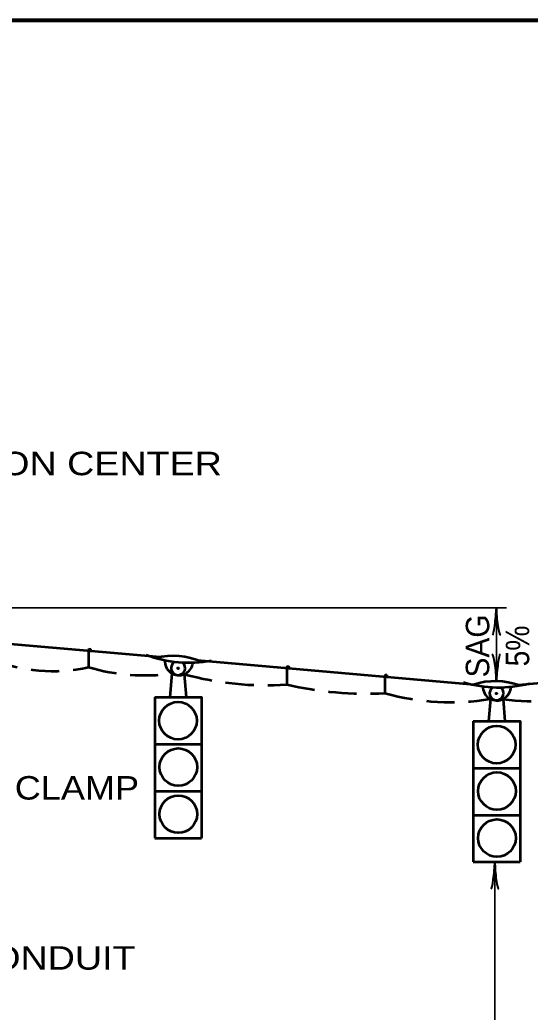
# Model space of a CAD drawing. Extents: x 14808 to 15663, y 10944 to 11488.
# Drawn here: x 15010.4 to 15075.7, y 11354.9 to 11481.7 of the extents above; entities that cross this region are included whole.
import ezdxf
from ezdxf.enums import TextEntityAlignment as Align

# ---------------------------------------------------------------- set-up
doc = ezdxf.new("R2010")
doc.units = 0
doc.header["$LTSCALE"] = 1.2
doc.linetypes.add('MEDIUM_DASHED', pattern=[4.5, 3, -1.5])
doc.layers.add('1', color=7, linetype='Continuous', lineweight=53)

msp = doc.modelspace()

# ---------------------------------------------------------------- linework, layer by layer
at = {"layer": '1', "lineweight": 35}
for p, q in [((14971.841, 11406.572), (15072.654, 11406.572)), ((15071.359, 11406.554), (15071.359, 11397.19)), ((15071.168, 11374.088), (15071.168, 11273.024))]:
    msp.add_line(p, q, dxfattribs=at)
at = {"layer": '1'}
for p, q in [((14985.033, 11404.084), (15028.363, 11400.293)), ((15158.822, 11404.102), (15074.187, 11396.698)), ((15019.242, 11401.332), (15019.221, 11401.093)), ((15019.237, 11401.272), (15019.221, 11401.093)), ((15019.237, 11401.272), (15019.416, 11401.257)), ((15019.259, 11401.331), (15019.238, 11401.092)), ((15019.253, 11401.271), (15019.238, 11401.092)), ((15019.242, 11401.332), (15019.481, 11401.311)), ((15019.277, 11401.329), (15019.256, 11401.09)), ((15019.272, 11401.269), (15019.256, 11401.09)), ((15019.295, 11401.328), (15019.274, 11401.088)), ((15019.29, 11401.268), (15019.274, 11401.088)), ((15019.313, 11401.326), (15019.292, 11401.087)), ((15019.308, 11401.266), (15019.292, 11401.087)), ((15019.322, 11401.325), (15019.301, 11401.086)), ((15019.335, 11401.324), (15019.314, 11401.085)), ((15019.33, 11401.264), (15019.314, 11401.085)), ((15019.349, 11401.323), (15019.328, 11401.084)), ((15019.344, 11401.263), (15019.328, 11401.084)), ((15019.362, 11401.322), (15019.341, 11401.083)), ((15019.372, 11401.321), (15019.351, 11401.082)), ((15019.366, 11401.261), (15019.351, 11401.082)), ((15019.39, 11401.319), (15019.369, 11401.08)), ((15019.385, 11401.259), (15019.369, 11401.08)), ((15019.408, 11401.318), (15019.387, 11401.079)), ((15019.402, 11401.258), (15019.387, 11401.078)), ((15019.422, 11401.316), (15019.401, 11401.077)), ((15019.416, 11401.257), (15019.401, 11401.077)), ((15019.435, 11401.315), (15019.414, 11401.076)), ((15019.446, 11401.314), (15019.425, 11401.075)), ((15019.458, 11401.313), (15019.437, 11401.074)), ((15019.47, 11401.312), (15019.449, 11401.073)), ((15019.481, 11401.311), (15019.461, 11401.072)), ((15019.221, 11401.093), (15019.401, 11401.077)), ((15019.221, 11401.093), (15019.221, 11398.993)), ((15019.221, 11401.093), (15019.461, 11401.072)), ((15033.144, 11399.874), (15068.526, 11396.779)), ((15044.577, 11399.117), (15044.556, 11398.877)), ((15044.572, 11399.057), (15044.556, 11398.877)), ((15044.556, 11398.877), (15044.735, 11398.862)), ((15044.556, 11398.877), (15044.556, 11396.777)), ((15044.556, 11398.877), (15044.795, 11398.856)), ((15044.593, 11399.115), (15044.572, 11398.876)), ((15044.572, 11399.057), (15044.751, 11399.041)), ((15044.588, 11399.055), (15044.572, 11398.876)), ((15044.577, 11399.117), (15044.816, 11399.096)), ((15044.611, 11399.114), (15044.59, 11398.874)), ((15044.606, 11399.054), (15044.59, 11398.874)), ((15044.629, 11399.112), (15044.608, 11398.873)), ((15044.624, 11399.052), (15044.608, 11398.873)), ((15044.647, 11399.11), (15044.626, 11398.871)), ((15044.642, 11399.051), (15044.626, 11398.871)), ((15044.657, 11399.11), (15044.636, 11398.871)), ((15044.669, 11399.109), (15044.649, 11398.869)), ((15044.664, 11399.049), (15044.649, 11398.869)), ((15044.683, 11399.107), (15044.662, 11398.868)), ((15044.678, 11399.047), (15044.662, 11398.868)), ((15044.696, 11399.106), (15044.675, 11398.867)), ((15044.706, 11399.105), (15044.685, 11398.866)), ((15044.701, 11399.045), (15044.685, 11398.866)), ((15044.724, 11399.104), (15044.703, 11398.865)), ((15044.719, 11399.044), (15044.703, 11398.864)), ((15044.742, 11399.102), (15044.721, 11398.863)), ((15044.737, 11399.042), (15044.721, 11398.863)), ((15044.756, 11399.101), (15044.735, 11398.862)), ((15044.751, 11399.041), (15044.735, 11398.862)), ((15044.769, 11399.1), (15044.748, 11398.861)), ((15044.781, 11399.099), (15044.76, 11398.86)), ((15044.793, 11399.098), (15044.772, 11398.859)), ((15044.805, 11399.096), (15044.784, 11398.857)), ((15044.816, 11399.096), (15044.795, 11398.856)), ((15029.878, 11398.178), (15029.613, 11395.151)), ((15031.457, 11398.102), (15031.715, 11395.151)), ((15057.129, 11398.018), (15057.108, 11397.779)), ((15057.124, 11397.959), (15057.108, 11397.779)), ((15057.108, 11397.779), (15057.287, 11397.764)), ((15057.108, 11397.779), (15057.108, 11395.679)), ((15057.108, 11397.779), (15057.347, 11397.758)), ((15057.145, 11398.017), (15057.124, 11397.778)), ((15057.124, 11397.959), (15057.303, 11397.943)), ((15057.14, 11397.957), (15057.124, 11397.778)), ((15057.129, 11398.018), (15057.368, 11397.997)), ((15057.163, 11398.015), (15057.142, 11397.776)), ((15057.158, 11397.956), (15057.142, 11397.776)), ((15057.181, 11398.014), (15057.16, 11397.775)), ((15057.176, 11397.954), (15057.16, 11397.775)), ((15057.2, 11398.012), (15057.178, 11397.773)), ((15057.194, 11397.952), (15057.178, 11397.773)), ((15057.209, 11398.011), (15057.188, 11397.772)), ((15057.222, 11398.01), (15057.201, 11397.771)), ((15057.216, 11397.95), (15057.201, 11397.771)), ((15057.235, 11398.009), (15057.214, 11397.77)), ((15057.23, 11397.949), (15057.214, 11397.77)), ((15057.248, 11398.008), (15057.227, 11397.769)), ((15057.258, 11398.007), (15057.237, 11397.768)), ((15057.253, 11397.947), (15057.237, 11397.768)), ((15057.276, 11398.005), (15057.255, 11397.766)), ((15057.271, 11397.946), (15057.255, 11397.766)), ((15057.294, 11398.004), (15057.273, 11397.765)), ((15057.289, 11397.944), (15057.273, 11397.765)), ((15057.308, 11398.003), (15057.287, 11397.764)), ((15057.303, 11397.943), (15057.287, 11397.764)), ((15057.321, 11398.001), (15057.3, 11397.762)), ((15057.333, 11398), (15057.312, 11397.761)), ((15057.345, 11397.999), (15057.324, 11397.76)), ((15057.357, 11397.998), (15057.336, 11397.759)), ((15057.368, 11397.997), (15057.347, 11397.758)), ((15027.667, 11395.151), (15027.667, 11377.151)), ((15070.606, 11394.931), (15070.357, 11392.088)), ((15072.211, 11394.921), (15072.459, 11392.088)), ((15068.411, 11392.088), (15068.411, 11374.088)), ((15027.667, 11389.151), (15033.667, 11389.151)), ((15068.411, 11386.088), (15074.411, 11386.088)), ((15027.667, 11383.151), (15033.667, 11383.151)), ((15068.411, 11380.088), (15074.411, 11380.088)), ((15027.667, 11377.151), (15033.667, 11377.151)), ((15068.411, 11374.088), (15074.411, 11374.088))]:
    msp.add_line(p, q, dxfattribs=at)
at = {"layer": '1', "lineweight": 158}
msp.add_lwpolyline([(15656.868, 11481.74), (14865.168, 11481.64), (14865.268, 10955.64)], dxfattribs=at)
at = {"layer": '1'}
for points in [[(15027.667, 11395.151), (15033.667, 11395.151), (15033.667, 11377.151)], [(15068.411, 11392.088), (15074.411, 11392.088), (15074.411, 11374.088)]]:
    msp.add_lwpolyline(points, dxfattribs=at)
for centre, radius in [((15030.653, 11398.849), 0.06), ((15071.371, 11395.629), 0.06), ((15030.653, 11392.155), 2.4), ((15071.397, 11389.092), 2.4), ((15030.691, 11386.218), 2.4), ((15071.435, 11383.155), 2.4), ((15030.691, 11380.206), 2.4), ((15071.435, 11377.143), 2.4)]:
    msp.add_circle(centre, radius, dxfattribs=at)
at = {"layer": '1', "linetype": 'MEDIUM_DASHED'}
for centre, radius, start, end in [((15014.662, 11419.161), 20.677, 247.26056, 282.73913), ((15026.463, 11423.601), 25.652, 253.60216, 277.64986), ((15041.877, 11435.709), 39.024, 254.5131, 273.93693), ((15054.64, 11439.753), 44.142, 256.79458, 273.20512), ((15065.542, 11425.691), 31.174, 254.30411, 279.34864), ((15076.777, 11429.205), 34.587, 262.41333, 283)]:
    msp.add_arc(centre, radius, start, end, dxfattribs=at)
at = {"layer": '1'}
for centre, radius, start, end in [((15032.047, 11415.001), 15.433, 249.20802, 280.79205), ((15029.993, 11391.39), 9.051, 65.93579, 103.97521), ((15030.763, 11399.751), 1.8, 174.85571, 355.14305), ((15030.672, 11398.887), 0.9, 118.90311, 51.34123), ((15071.636, 11411.839), 15.433, 253.20802, 284.79205), ((15071.233, 11388.143), 9.051, 69.93579, 107.97521), ((15071.418, 11396.537), 1.8, 178.85571, 359.14305), ((15071.388, 11395.668), 0.9, 122.90311, 55.34123)]:
    msp.add_arc(centre, radius, start, end, dxfattribs=at)
at = {"layer": '1', "lineweight": 40}
for centre, major_axis, ratio, start_param, end_param in [((15071.105, 11405.209), (-0.211, -2.108), 0.07063, 6.2823074, 8.5597026), ((15071.691, 11405.244), (-0.187, 2.143), 0.122415, 0.8963533, 3.1415927), ((15071.028, 11398.499), (0.187, -2.143), 0.122415, 0.8963533, 3.1415927), ((15071.613, 11398.534), (0.211, 2.108), 0.07063, 6.2823074, 8.5597026), ((15070.914, 11372.744), (-0.211, -2.108), 0.07063, 6.2823074, 8.5597026), ((15071.5, 11372.779), (-0.187, 2.143), 0.122415, 0.8963533, 3.1415927)]:
    msp.add_ellipse(centre, major_axis=major_axis, ratio=ratio, start_param=start_param, end_param=end_param, dxfattribs=at)

# ---------------------------------------------------------------- texts
at = {"layer": '1'}
for s, width, p in [('CLAMPS 1.2m ON CENTER', 1.2, (14974.739, 11423.529)), ('THREE BOLT CLAMP', 1.15, (14979.528, 11382.066))]:
    msp.add_text(s, height=3, dxfattribs=dict(at, width=width)).set_placement(p)
for s, width, p in [('SAG', 0.95, (15070.45, 11401.7)), ('5%', 0.9, (15075.562, 11401.7))]:
    msp.add_text(s, height=3, rotation=90, dxfattribs=dict(at, width=width)).set_placement(p, align=Align.CENTER)
at = {"layer": '1', "width": 1.2}
msp.add_text('31.8mm STEEL CONDUIT', height=3, dxfattribs=at).set_placement((15025.221, 11360.32), align=Align.RIGHT)

doc.saveas('drawing.dxf')
